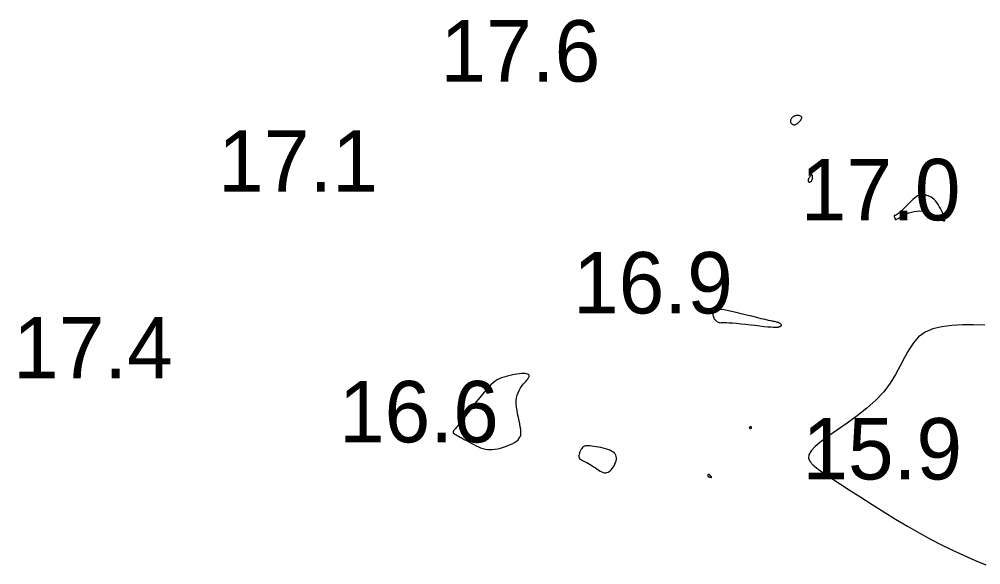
# Model space of a CAD drawing. Extents: x 3040093 to 3056816, y 408076 to 509144.
# Drawn here: x 3045488.1 to 3045566.4, y 433778.6 to 433823 of the extents above; entities that cross this region are included whole.
import ezdxf

# ---------------------------------------------------------------- set-up
doc = ezdxf.new("R2010")
doc.units = 0
doc.layers.add('V-CHAN-CONT-EL17', color=7, linetype='Continuous')
doc.layers.add('V-TOPO-SOUN-0610', color=7, linetype='Continuous')

msp = doc.modelspace()

# ---------------------------------------------------------------- linework, layer by layer
at = {"layer": 'V-CHAN-CONT-EL17'}
for points in [[(3045550.928, 433814.613), (3045550.944, 433814.568), (3045550.967, 433814.525), (3045550.997, 433814.484), (3045551.032, 433814.448), (3045551.071, 433814.417), (3045551.114, 433814.392), (3045551.159, 433814.375), (3045551.205, 433814.365), (3045551.252, 433814.364), (3045551.301, 433814.371), (3045551.351, 433814.386), (3045551.402, 433814.409), (3045551.454, 433814.439), (3045551.508, 433814.477), (3045551.563, 433814.522), (3045551.619, 433814.574), (3045551.674, 433814.631), (3045551.726, 433814.691), (3045551.772, 433814.753), (3045551.809, 433814.814), (3045551.836, 433814.873), (3045551.849, 433814.928), (3045551.847, 433814.976), (3045551.827, 433815.017), (3045551.793, 433815.05), (3045551.746, 433815.076), (3045551.69, 433815.095), (3045551.629, 433815.108), (3045551.565, 433815.116), (3045551.5, 433815.12), (3045551.44, 433815.119), (3045551.384, 433815.114), (3045551.334, 433815.105), (3045551.289, 433815.093), (3045551.248, 433815.078), (3045551.21, 433815.058), (3045551.173, 433815.036), (3045551.138, 433815.01), (3045551.104, 433814.98), (3045551.069, 433814.948), (3045551.035, 433814.912), (3045551.004, 433814.874), (3045550.976, 433814.834), (3045550.952, 433814.792), (3045550.934, 433814.749), (3045550.924, 433814.704), (3045550.921, 433814.658)], [(3045552.445, 433810.056), (3045552.426, 433810.022), (3045552.41, 433809.99), (3045552.398, 433809.96), (3045552.389, 433809.932), (3045552.382, 433809.904), (3045552.378, 433809.878), (3045552.377, 433809.852), (3045552.377, 433809.826), (3045552.38, 433809.801), (3045552.385, 433809.777), (3045552.393, 433809.755), (3045552.404, 433809.736), (3045552.418, 433809.721), (3045552.436, 433809.709), (3045552.457, 433809.702), (3045552.482, 433809.7), (3045552.51, 433809.704), (3045552.54, 433809.714), (3045552.571, 433809.731), (3045552.601, 433809.754), (3045552.63, 433809.785), (3045552.657, 433809.823), (3045552.68, 433809.869), (3045552.699, 433809.924), (3045552.714, 433809.983), (3045552.723, 433810.045), (3045552.728, 433810.106), (3045552.728, 433810.162), (3045552.723, 433810.212), (3045552.712, 433810.251), (3045552.696, 433810.276), (3045552.674, 433810.286), (3045552.648, 433810.282), (3045552.619, 433810.265), (3045552.588, 433810.24), (3045552.556, 433810.207), (3045552.524, 433810.17), (3045552.495, 433810.131), (3045552.468, 433810.092)], [(3045559.458, 433806.706), (3045559.46, 433806.691), (3045559.46, 433806.677), (3045559.461, 433806.664), (3045559.463, 433806.653), (3045559.466, 433806.644), (3045559.471, 433806.638), (3045559.479, 433806.636), (3045559.49, 433806.638), (3045559.508, 433806.646), (3045559.535, 433806.66), (3045559.573, 433806.681), (3045559.626, 433806.712), (3045559.696, 433806.752), (3045559.787, 433806.804), (3045559.9, 433806.868), (3045560.038, 433806.943), (3045560.199, 433807.027), (3045560.38, 433807.111), (3045560.577, 433807.192), (3045560.787, 433807.262), (3045561.007, 433807.316), (3045561.235, 433807.348), (3045561.467, 433807.352), (3045561.7, 433807.324), (3045561.93, 433807.269), (3045562.154, 433807.193), (3045562.369, 433807.102), (3045562.571, 433807.004), (3045562.755, 433806.904), (3045562.92, 433806.81), (3045563.061, 433806.727), (3045563.176, 433806.662), (3045563.266, 433806.612), (3045563.336, 433806.577), (3045563.388, 433806.555), (3045563.426, 433806.543), (3045563.453, 433806.541), (3045563.471, 433806.545), (3045563.485, 433806.554), (3045563.497, 433806.567), (3045563.505, 433806.586), (3045563.51, 433806.613), (3045563.508, 433806.651), (3045563.5, 433806.702), (3045563.482, 433806.769), (3045563.455, 433806.853), (3045563.416, 433806.959), (3045563.365, 433807.086), (3045563.301, 433807.231), (3045563.227, 433807.388), (3045563.143, 433807.552), (3045563.051, 433807.717), (3045562.951, 433807.878), (3045562.845, 433808.03), (3045562.734, 433808.166), (3045562.618, 433808.283), (3045562.5, 433808.382), (3045562.381, 433808.463), (3045562.262, 433808.529), (3045562.146, 433808.582), (3045562.033, 433808.623), (3045561.925, 433808.654), (3045561.824, 433808.676), (3045561.73, 433808.691), (3045561.642, 433808.698), (3045561.555, 433808.692), (3045561.467, 433808.673), (3045561.375, 433808.637), (3045561.276, 433808.583), (3045561.165, 433808.506), (3045561.041, 433808.406), (3045560.901, 433808.281), (3045560.749, 433808.136), (3045560.589, 433807.979), (3045560.426, 433807.816), (3045560.265, 433807.653), (3045560.11, 433807.499), (3045559.966, 433807.36), (3045559.838, 433807.242), (3045559.729, 433807.152), (3045559.639, 433807.086), (3045559.565, 433807.04), (3045559.506, 433807.01), (3045559.46, 433806.993), (3045559.425, 433806.984), (3045559.4, 433806.978), (3045559.383, 433806.972), (3045559.372, 433806.962), (3045559.366, 433806.949), (3045559.364, 433806.933), (3045559.366, 433806.914), (3045559.371, 433806.894), (3045559.378, 433806.874), (3045559.387, 433806.854), (3045559.396, 433806.835), (3045559.406, 433806.818), (3045559.416, 433806.802), (3045559.425, 433806.787), (3045559.433, 433806.773), (3045559.441, 433806.76), (3045559.447, 433806.747), (3045559.452, 433806.734), (3045559.456, 433806.72)], [(3045546.53, 433798.213), (3045546.889, 433798.178), (3045547.275, 433798.136), (3045547.673, 433798.091), (3045548.069, 433798.046), (3045548.448, 433798.002), (3045548.796, 433797.963), (3045549.097, 433797.931), (3045549.342, 433797.909), (3045549.534, 433797.895), (3045549.68, 433797.889), (3045549.789, 433797.889), (3045549.869, 433797.895), (3045549.926, 433797.904), (3045549.969, 433797.916), (3045550.006, 433797.929), (3045550.043, 433797.943), (3045550.079, 433797.958), (3045550.113, 433797.973), (3045550.144, 433797.99), (3045550.169, 433798.008), (3045550.187, 433798.028), (3045550.196, 433798.05), (3045550.195, 433798.074), (3045550.182, 433798.101), (3045550.158, 433798.13), (3045550.126, 433798.16), (3045550.087, 433798.189), (3045550.043, 433798.217), (3045549.996, 433798.243), (3045549.948, 433798.266), (3045549.9, 433798.285), (3045549.852, 433798.3), (3045549.798, 433798.313), (3045549.73, 433798.327), (3045549.639, 433798.344), (3045549.517, 433798.368), (3045549.356, 433798.402), (3045549.147, 433798.447), (3045548.883, 433798.509), (3045548.558, 433798.586), (3045548.185, 433798.678), (3045547.779, 433798.778), (3045547.354, 433798.882), (3045546.928, 433798.984), (3045546.514, 433799.082), (3045546.129, 433799.169), (3045545.787, 433799.241), (3045545.501, 433799.294), (3045545.268, 433799.329), (3045545.083, 433799.346), (3045544.939, 433799.348), (3045544.83, 433799.336), (3045544.75, 433799.31), (3045544.694, 433799.273), (3045544.654, 433799.225), (3045544.627, 433799.168), (3045544.611, 433799.104), (3045544.604, 433799.034), (3045544.606, 433798.96), (3045544.617, 433798.884), (3045544.636, 433798.807), (3045544.661, 433798.73), (3045544.693, 433798.657), (3045544.73, 433798.587), (3045544.772, 433798.522), (3045544.818, 433798.463), (3045544.869, 433798.41), (3045544.923, 433798.365), (3045544.979, 433798.327), (3045545.038, 433798.297), (3045545.098, 433798.276), (3045545.161, 433798.265), (3045545.232, 433798.261), (3045545.318, 433798.262), (3045545.426, 433798.264), (3045545.562, 433798.266), (3045545.735, 433798.264), (3045545.949, 433798.257), (3045546.214, 433798.24)], [(3045523.516, 433789.234), (3045523.536, 433789.223), (3045523.563, 433789.21), (3045523.6, 433789.193), (3045523.65, 433789.169), (3045523.716, 433789.135), (3045523.802, 433789.089), (3045523.911, 433789.03), (3045524.043, 433788.954), (3045524.197, 433788.864), (3045524.368, 433788.765), (3045524.551, 433788.66), (3045524.744, 433788.551), (3045524.941, 433788.443), (3045525.139, 433788.339), (3045525.333, 433788.243), (3045525.52, 433788.157), (3045525.703, 433788.083), (3045525.884, 433788.023), (3045526.066, 433787.977), (3045526.251, 433787.946), (3045526.444, 433787.932), (3045526.647, 433787.935), (3045526.863, 433787.957), (3045527.093, 433787.998), (3045527.333, 433788.057), (3045527.576, 433788.13), (3045527.816, 433788.215), (3045528.046, 433788.31), (3045528.262, 433788.413), (3045528.455, 433788.52), (3045528.62, 433788.63), (3045528.751, 433788.74), (3045528.851, 433788.854), (3045528.922, 433788.974), (3045528.967, 433789.105), (3045528.987, 433789.249), (3045528.987, 433789.411), (3045528.968, 433789.593), (3045528.934, 433789.798), (3045528.887, 433790.03), (3045528.832, 433790.283), (3045528.774, 433790.552), (3045528.717, 433790.829), (3045528.668, 433791.11), (3045528.63, 433791.388), (3045528.609, 433791.658), (3045528.609, 433791.912), (3045528.635, 433792.147), (3045528.683, 433792.362), (3045528.749, 433792.557), (3045528.828, 433792.735), (3045528.918, 433792.896), (3045529.013, 433793.041), (3045529.11, 433793.172), (3045529.204, 433793.288), (3045529.291, 433793.392), (3045529.371, 433793.484), (3045529.442, 433793.566), (3045529.505, 433793.639), (3045529.558, 433793.705), (3045529.601, 433793.765), (3045529.633, 433793.82), (3045529.653, 433793.873), (3045529.661, 433793.923), (3045529.655, 433793.97), (3045529.632, 433794.012), (3045529.591, 433794.05), (3045529.53, 433794.08), (3045529.446, 433794.103), (3045529.338, 433794.117), (3045529.203, 433794.121), (3045529.041, 433794.114), (3045528.856, 433794.097), (3045528.653, 433794.07), (3045528.44, 433794.035), (3045528.22, 433793.992), (3045528.001, 433793.942), (3045527.788, 433793.886), (3045527.586, 433793.826), (3045527.4, 433793.76), (3045527.225, 433793.685), (3045527.057, 433793.596), (3045526.891, 433793.488), (3045526.72, 433793.355), (3045526.54, 433793.193), (3045526.346, 433792.996), (3045526.131, 433792.759), (3045525.893, 433792.48), (3045525.637, 433792.169), (3045525.371, 433791.836), (3045525.102, 433791.493), (3045524.838, 433791.153), (3045524.587, 433790.827), (3045524.356, 433790.527), (3045524.153, 433790.265), (3045523.983, 433790.05), (3045523.845, 433789.878), (3045523.735, 433789.744), (3045523.649, 433789.642), (3045523.585, 433789.566), (3045523.539, 433789.509), (3045523.506, 433789.467), (3045523.484, 433789.432), (3045523.47, 433789.4), (3045523.461, 433789.371), (3045523.458, 433789.343), (3045523.46, 433789.318), (3045523.466, 433789.296), (3045523.475, 433789.276), (3045523.487, 433789.259), (3045523.501, 433789.245)], [(3045547.608, 433789.677), (3045547.62, 433789.67), (3045547.633, 433789.664), (3045547.648, 433789.66), (3045547.664, 433789.657), (3045547.679, 433789.656), (3045547.695, 433789.656), (3045547.71, 433789.66), (3045547.724, 433789.666), (3045547.737, 433789.674), (3045547.749, 433789.683), (3045547.758, 433789.694), (3045547.765, 433789.705), (3045547.77, 433789.717), (3045547.772, 433789.728), (3045547.771, 433789.739), (3045547.767, 433789.748), (3045547.76, 433789.756), (3045547.751, 433789.762), (3045547.739, 433789.768), (3045547.727, 433789.772), (3045547.713, 433789.775), (3045547.698, 433789.777), (3045547.684, 433789.777), (3045547.67, 433789.777), (3045547.657, 433789.775), (3045547.644, 433789.773), (3045547.633, 433789.769), (3045547.622, 433789.765), (3045547.612, 433789.76), (3045547.603, 433789.754), (3045547.596, 433789.748), (3045547.59, 433789.741), (3045547.585, 433789.733), (3045547.583, 433789.725), (3045547.581, 433789.717), (3045547.582, 433789.709), (3045547.585, 433789.7), (3045547.59, 433789.692), (3045547.598, 433789.684)], [(3045534.621, 433786.73), (3045534.761, 433786.637), (3045534.903, 433786.539), (3045535.043, 433786.439), (3045535.182, 433786.342), (3045535.317, 433786.252), (3045535.446, 433786.174), (3045535.568, 433786.112), (3045535.683, 433786.069), (3045535.79, 433786.045), (3045535.89, 433786.041), (3045535.985, 433786.055), (3045536.076, 433786.088), (3045536.163, 433786.138), (3045536.247, 433786.205), (3045536.331, 433786.288), (3045536.414, 433786.387), (3045536.493, 433786.498), (3045536.567, 433786.619), (3045536.633, 433786.747), (3045536.687, 433786.878), (3045536.728, 433787.009), (3045536.752, 433787.137), (3045536.757, 433787.259), (3045536.741, 433787.373), (3045536.704, 433787.477), (3045536.645, 433787.574), (3045536.566, 433787.662), (3045536.467, 433787.743), (3045536.348, 433787.817), (3045536.21, 433787.884), (3045536.054, 433787.945), (3045535.88, 433788.001), (3045535.693, 433788.05), (3045535.499, 433788.093), (3045535.302, 433788.131), (3045535.107, 433788.163), (3045534.921, 433788.189), (3045534.748, 433788.21), (3045534.593, 433788.225), (3045534.46, 433788.234), (3045534.348, 433788.236), (3045534.253, 433788.23), (3045534.173, 433788.215), (3045534.104, 433788.189), (3045534.043, 433788.151), (3045533.988, 433788.1), (3045533.934, 433788.034), (3045533.881, 433787.954), (3045533.83, 433787.861), (3045533.783, 433787.761), (3045533.744, 433787.656), (3045533.716, 433787.551), (3045533.701, 433787.449), (3045533.702, 433787.354), (3045533.723, 433787.27), (3045533.764, 433787.199), (3045533.826, 433787.14), (3045533.904, 433787.088), (3045533.998, 433787.04), (3045534.106, 433786.992), (3045534.224, 433786.94), (3045534.35, 433786.881), (3045534.484, 433786.812)], [(3045544.51, 433785.68), (3045544.503, 433785.698), (3045544.49, 433785.719), (3045544.473, 433785.743), (3045544.452, 433785.769), (3045544.429, 433785.796), (3045544.404, 433785.821), (3045544.378, 433785.845), (3045544.353, 433785.866), (3045544.328, 433785.884), (3045544.305, 433785.898), (3045544.283, 433785.908), (3045544.263, 433785.914), (3045544.245, 433785.915), (3045544.23, 433785.911), (3045544.217, 433785.902), (3045544.208, 433785.888), (3045544.203, 433785.87), (3045544.199, 433785.848), (3045544.199, 433785.825), (3045544.201, 433785.802), (3045544.205, 433785.78), (3045544.211, 433785.76), (3045544.219, 433785.743), (3045544.228, 433785.731), (3045544.239, 433785.722), (3045544.251, 433785.717), (3045544.265, 433785.714), (3045544.281, 433785.712), (3045544.3, 433785.71), (3045544.32, 433785.707), (3045544.343, 433785.702), (3045544.369, 433785.695), (3045544.395, 433785.687), (3045544.422, 433785.678), (3045544.447, 433785.67), (3045544.47, 433785.664), (3045544.489, 433785.661), (3045544.503, 433785.662), (3045544.51, 433785.668)]]:
    msp.add_lwpolyline(points, close=True, dxfattribs=at)
msp.add_lwpolyline([(3045566.768, 433798.07), (3045565.847, 433798.079), (3045564.942, 433798.072), (3045564.072, 433798.029), (3045563.26, 433797.929), (3045562.525, 433797.754), (3045561.89, 433797.481), (3045561.368, 433797.098), (3045560.936, 433796.616), (3045560.563, 433796.052), (3045560.219, 433795.425), (3045559.873, 433794.752), (3045559.496, 433794.05), (3045559.055, 433793.338), (3045558.521, 433792.634), (3045557.873, 433791.952), (3045557.138, 433791.299), (3045556.352, 433790.678), (3045555.552, 433790.093), (3045554.773, 433789.548), (3045554.053, 433789.046), (3045553.429, 433788.591), (3045552.936, 433788.186), (3045552.603, 433787.832), (3045552.431, 433787.518), (3045552.41, 433787.227), (3045552.533, 433786.944), (3045552.79, 433786.654), (3045553.174, 433786.343), (3045553.676, 433785.994), (3045554.289, 433785.593), (3045555.001, 433785.129), (3045555.798, 433784.611), (3045556.663, 433784.053), (3045557.579, 433783.47), (3045558.529, 433782.874), (3045559.496, 433782.282), (3045560.463, 433781.705), (3045561.413, 433781.159), (3045562.334, 433780.653), (3045563.233, 433780.185), (3045564.123, 433779.749), (3045565.014, 433779.337), (3045565.919, 433778.943), (3045566.849, 433778.56)], dxfattribs=at)

# ---------------------------------------------------------------- texts
at = {"layer": 'V-TOPO-SOUN-0610'}
for s, p in [('17.6 ', (3045522.433, 433817.88)), ('17.1 ', (3045504.323, 433808.92)), ('17.0 ', (3045551.763, 433806.59)), ('16.9 ', (3045533.223, 433799.01)), ('17.4 ', (3045487.623, 433793.73)), ('16.6 ', (3045514.163, 433788.52)), ('15.9 ', (3045551.893, 433785.5))]:
    msp.add_text(s, height=5, dxfattribs=at).set_placement(p)

doc.saveas('drawing.dxf')
